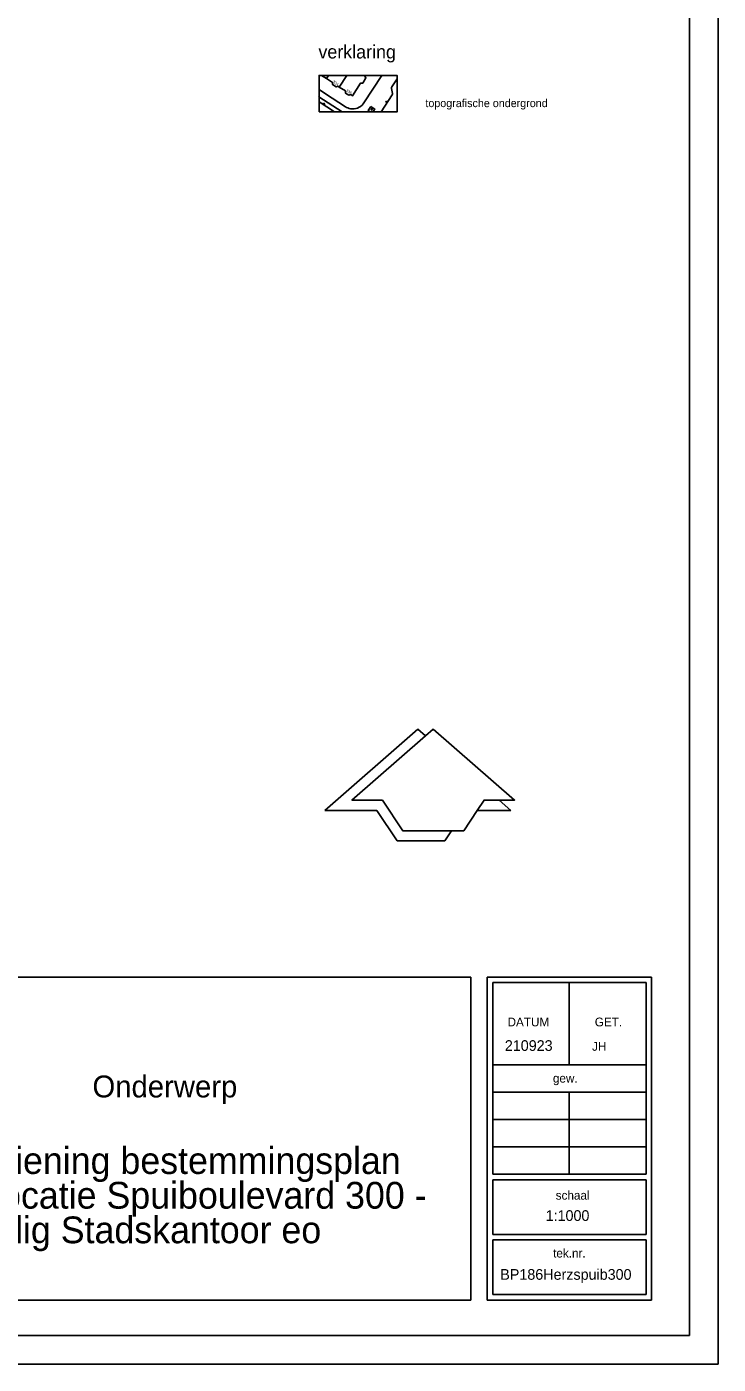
# Model space of a CAD drawing. Extents: x 104705 to 105186, y 424858 to 425816.
# Drawn here: x 105089 to 105186, y 424857.8 to 425045.2 of the extents above; entities that cross this region are included whole.
import ezdxf

# ---------------------------------------------------------------- set-up
doc = ezdxf.new("R2010")
doc.units = 0
for name, color, linetype in [('BP_ALG_kader', 7, 'Continuous'), ('BP_ALG_legenda', 7, 'Continuous'), ('BP_ALG_noordpijl', 7, 'Continuous'), ('BP_ALG_stempel', 7, 'Continuous'), ('BP_TXT_tekst', 7, 'Continuous')]:
    doc.layers.add(name, color=color, linetype=linetype)

msp = doc.modelspace()

# ---------------------------------------------------------------- linework, layer by layer
at = {"layer": 'BP_ALG_kader'}
for p, q in [((105186, 425197.96), (105186, 424857.76)), ((105181.95, 424861.81), (105181.95, 425193.91)), ((104708.91, 424861.81), (105181.95, 424861.81)), ((105186, 424857.76), (104704.86, 424857.76))]:
    msp.add_line(p, q, dxfattribs=at)
at = {"layer": 'BP_ALG_legenda'}
for p, q in [((105133.93, 425038.41), (105132.87, 425036.78)), ((105130.09, 425036.39), (105130.03, 425036.43)), ((105131.85, 425035.25), (105130.09, 425036.39)), ((105132.19, 425033.31), (105130.03, 425034.71)), ((105130.57, 425034.37), (105130.67, 425034.53)), ((105130.73, 425034.27), (105130.57, 425034.37)), ((105130.67, 425034.53), (105130.83, 425034.43)), ((105130.83, 425034.43), (105130.73, 425034.27)), ((105138.74, 425033.31), (105139.26, 425034.12)), ((105139.39, 425034.67), (105139.5, 425034.82)), ((105139.55, 425034.56), (105139.39, 425034.67)), ((105139.5, 425034.82), (105139.65, 425034.72)), ((105139.65, 425034.72), (105139.55, 425034.56))]:
    msp.add_line(p, q, dxfattribs=at)
msp.add_lwpolyline([(105130.03, 425033.31), (105140.98, 425033.31), (105140.98, 425038.41), (105130.03, 425038.41)], close=True, dxfattribs=at)
for points in [[(105130.39, 425038.41), (105131.08, 425037.97)], [(105131.08, 425037.97), (105131.37, 425038.41)], [(105131.08, 425037.97), (105131.91, 425037.43), (105131.92, 425037.13), (105132.45, 425036.8), (105132.68, 425036.9), (105132.87, 425036.78)], [(105138.85, 425038.41), (105136.33, 425034.56), (105136.23, 425034.42), (105136.07, 425034.25), (105135.86, 425034.08), (105135.66, 425033.95), (105135.42, 425033.84), (105135.19, 425033.77), (105134.93, 425033.73), (105134.66, 425033.73), (105134.42, 425033.75), (105134.23, 425033.8), (105134.07, 425033.85), (105133.88, 425033.94), (105133.72, 425034.03), (105131.85, 425035.25)], [(105132.87, 425036.78), (105133.72, 425036.24), (105133.74, 425035.92), (105134.2, 425035.65), (105134.5, 425035.72), (105134.73, 425035.56), (105135.86, 425037.33), (105136.16, 425037.33), (105136.61, 425038.07), (105136.46, 425038.32), (105136.52, 425038.41)], [(105139.26, 425034.12), (105140.29, 425035.7), (105140.31, 425035.78), (105140.32, 425035.89), (105140.18, 425036.59), (105140.2, 425036.71), (105140.24, 425036.81), (105140.98, 425037.94)], [(105130.02, 425035.43), (105130.06, 425035.5), (105130.03, 425035.52)], [(105130.02, 425035.43), (105133.28, 425033.31)], [(105137.28, 425034.08), (105136.9, 425033.51), (105137.2, 425033.31)], [(105137.58, 425033.31), (105137.84, 425033.7), (105137.28, 425034.08)]]:
    msp.add_lwpolyline(points, dxfattribs=at)
msp.add_circle((105137.41, 425033.66), 0.0938, dxfattribs=at)
at = {"layer": 'BP_ALG_noordpijl'}
for p, q in [((105130.85, 424935.4), (105143.88, 424946.8)), ((105143.88, 424946.8), (105130.85, 424935.4)), ((105143.88, 424946.8), (105144.96, 424945.86)), ((105144.96, 424945.86), (105143.88, 424946.8)), ((105144.96, 424945.86), (105146.04, 424946.8)), ((105155.28, 424936.83), (105156.91, 424935.4)), ((105138.15, 424935.4), (105130.85, 424935.4)), ((105130.85, 424935.4), (105138.15, 424935.4)), ((105141, 424931.13), (105138.15, 424935.4)), ((105138.15, 424935.4), (105141, 424931.13)), ((105138.2, 424935.4), (105138.2, 424935.4)), ((105156.91, 424935.4), (105152.22, 424935.4)), ((105156.38, 424935.4), (105156.38, 424935.4)), ((105156.73, 424935.4), (105156.73, 424935.4)), ((105147.66, 424931.13), (105141, 424931.13)), ((105141, 424931.13), (105147.66, 424931.13)), ((105141.05, 424931.13), (105141.05, 424931.13)), ((105147.11, 424931.13), (105147.11, 424931.13)), ((105147.47, 424931.13), (105147.47, 424931.13)), ((105148.61, 424932.55), (105147.66, 424931.13)), ((105147.66, 424931.13), (105148.61, 424932.55)), ((105148.36, 424932.2), (105148.36, 424932.2))]:
    msp.add_line(p, q, dxfattribs=at)
for points in [[(105144.96, 424945.86), (105134.64, 424936.83), (105138.92, 424936.83), (105141.77, 424932.55), (105148.61, 424932.55)], [(105148.61, 424932.55), (105141.77, 424932.55), (105138.92, 424936.83), (105134.64, 424936.83), (105144.96, 424945.86)], [(105146.04, 424946.8), (105157.45, 424936.83), (105155.28, 424936.83)], [(105152.22, 424935.4), (105153.17, 424936.83), (105155.28, 424936.83)], [(105152.22, 424935.4), (105150.32, 424932.55), (105148.61, 424932.55)]]:
    msp.add_lwpolyline(points, dxfattribs=at)
at = {"layer": 'BP_ALG_stempel'}
for p, q in [((105151.31, 424912.03), (105067.66, 424912.03)), ((105151.31, 424912.03), (105151.31, 424866.75)), ((105153.61, 424912.03), (105153.61, 424866.75)), ((105176.64, 424912.03), (105153.61, 424912.03)), ((105175.87, 424911.26), (105154.38, 424911.26)), ((105154.38, 424911.26), (105154.38, 424884.4)), ((105165.12, 424911.26), (105165.12, 424899.75)), ((105175.87, 424884.4), (105175.87, 424911.26)), ((105176.64, 424866.75), (105176.64, 424912.03)), ((105154.38, 424899.75), (105175.87, 424899.75)), ((105154.38, 424895.91), (105175.87, 424895.91)), ((105165.12, 424895.91), (105165.12, 424884.4)), ((105154.38, 424892.08), (105175.87, 424892.08)), ((105154.38, 424888.24), (105175.87, 424888.24)), ((105154.38, 424884.4), (105175.87, 424884.4)), ((105154.38, 424875.96), (105154.38, 424883.63)), ((105154.38, 424883.63), (105175.87, 424883.63)), ((105175.87, 424875.96), (105175.87, 424883.63)), ((105154.38, 424875.96), (105175.87, 424875.96)), ((105154.38, 424867.52), (105154.38, 424875.19)), ((105154.38, 424875.19), (105175.87, 424875.19)), ((105175.87, 424867.52), (105175.87, 424875.19)), ((105154.38, 424867.52), (105175.87, 424867.52)), ((105067.66, 424866.75), (105151.31, 424866.75)), ((105153.61, 424866.75), (105176.64, 424866.75))]:
    msp.add_line(p, q, dxfattribs=at)

# ---------------------------------------------------------------- texts
for s, height, p in [('DATUM', 1.228, (105156.46, 424905.12)), ('GET.', 1.228, (105168.69, 424905.12)), ('     JH', 1.228, (105166.03, 424901.7)), ('Onderwerp ', 3.07, (105098.26, 424895.16)), ('gew.', 1.228, (105162.82, 424897.24)), ('schaal', 1.228, (105163.21, 424880.83)), ('tek.nr.', 1.228, (105162.85, 424872.72))]:
    msp.add_text(s, height=height, dxfattribs=at).set_placement(p)
at = {"layer": 'BP_TXT_tekst'}
for s, height, p in [('verklaring', 1.875, (105129.94, 425040.79)), ('topografische ondergrond', 1.125, (105144.94, 425033.97)), ('210923', 1.5, (105156.08, 424901.68)), ('9e herziening bestemmingsplan ', 3.75, (105070.68, 424884.43)), ('Schil, locatie Spuiboulevard 300 -', 3.75, (105070.68, 424879.57)), ('voormalig Stadskantoor eo', 3.75, (105070.68, 424874.72)), ('1:1000', 1.5, (105161.8, 424877.85)), ('BP186Herzspuib300', 1.5, (105155.44, 424869.6))]:
    msp.add_text(s, height=height, dxfattribs=at).set_placement(p)
for s, p in [('334', (105131.91, 425037.43)), ('336', (105133.75, 425036.23))]:
    msp.add_text(s, height=0.375, rotation=327.0354, dxfattribs=at).set_placement(p)

doc.saveas('drawing.dxf')
